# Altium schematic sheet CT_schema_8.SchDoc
size 147 x 119 mm
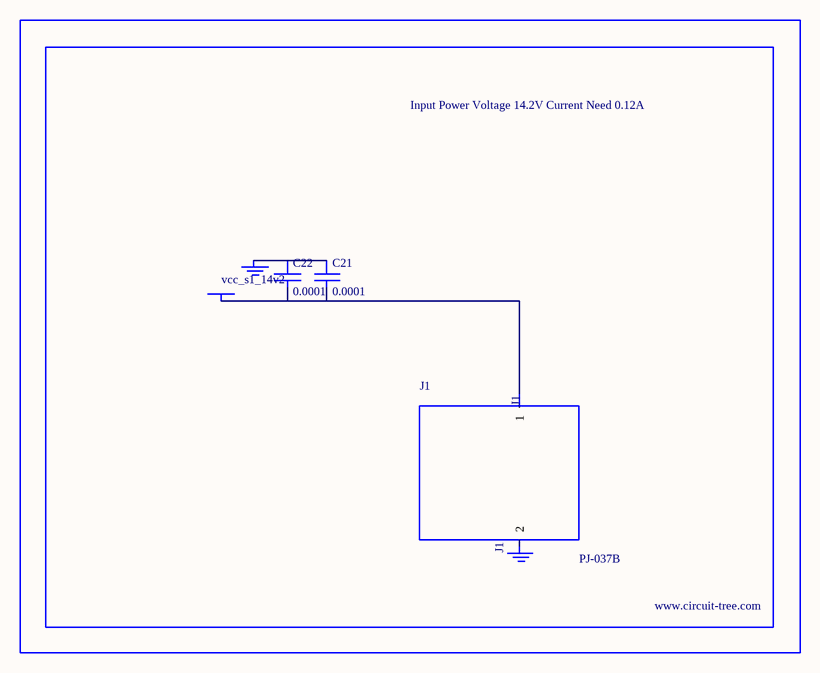
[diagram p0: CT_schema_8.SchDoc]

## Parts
BORDER7  (no value)
C21  0.0001  [EXV-9H]
C22  0.0001  [EXV-9H]
GND_INSTANCE_7_0  (no value)
GND_INSTANCE_7_1  (no value)
J1  PJ-037B  [PJ-037B_PACKAGE]
POWER_INSTANCE_7_0  vcc_s1_14v2

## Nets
NetC21_1: C21.1 C22.1 GND_INSTANCE_7_0.0(GND)
NetC21_2: C21.2 C22.2 J1.1 POWER_INSTANCE_7_0.0(PWR)

Not connected (* = marked no-connect by the designer): GND_INSTANCE_7_1 0(GND); J1 2

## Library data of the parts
BORDER7 = BORDER_PAGE7
C21 C22 = EDK107M035A9HAA
GND_INSTANCE_7_0 GND_INSTANCE_7_1 = GND
POWER_INSTANCE_7_0 = PWR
